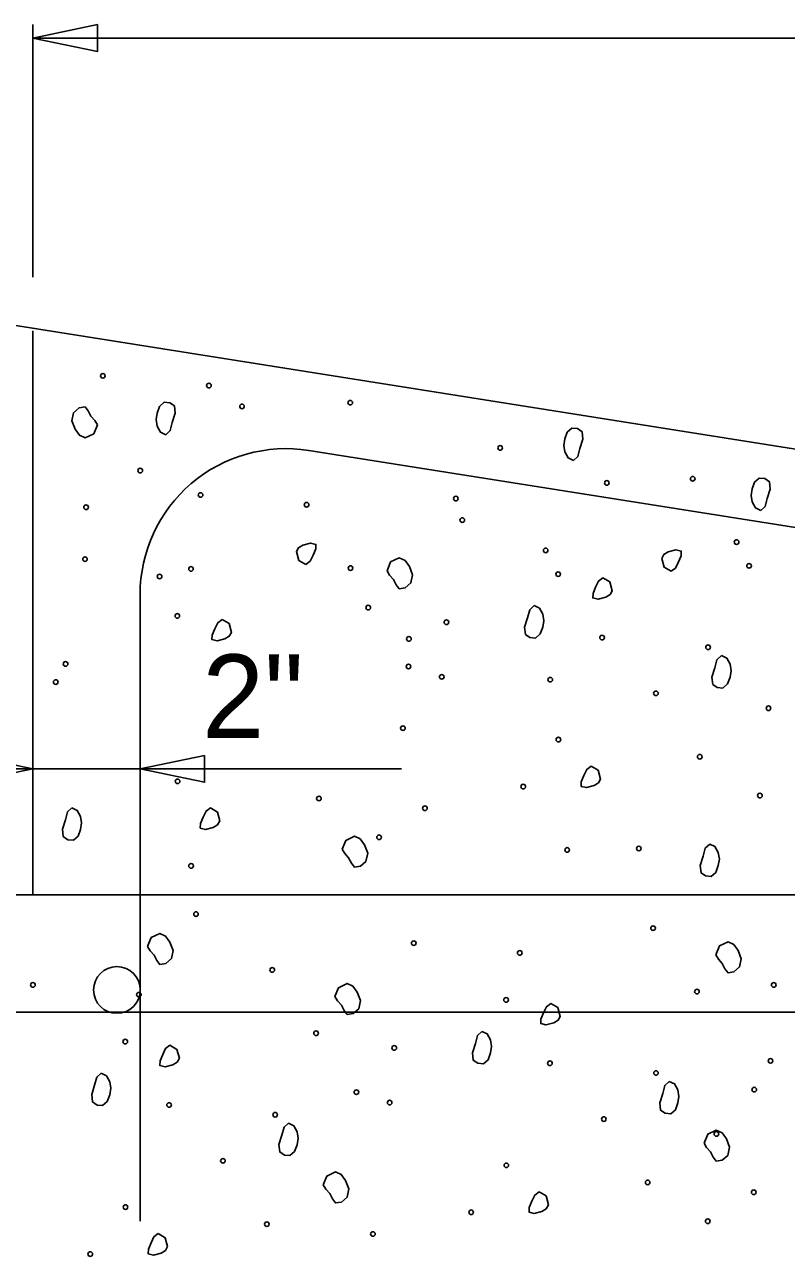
# Model space of a CAD drawing. Extents: x -439.2 to -407.9, y -458.1 to -436.2.
# Drawn here: x -422.056 to -420.686, y -450.425 to -448.209 of the extents above; entities that cross this region are included whole.
import ezdxf

# ---------------------------------------------------------------- set-up
doc = ezdxf.new("R2010")
doc.units = 0
doc.layers.add('Level 4', color=7, linetype='Continuous')
doc.layers.add('Level 45', color=7, linetype='Continuous')

msp = doc.modelspace()

# ---------------------------------------------------------------- linework, layer by layer
at = {"layer": 'Level 4'}
for p, q in [((-422.0412, -448.6637), (-422.0412, -448.2093)), ((-422.0412, -448.2334), (-416.5408, -448.2334)), ((-423.4518, -448.532), (-416.5407, -449.6272)), ((-422.0416, -448.7599), (-422.0416, -449.7752)), ((-421.5448, -448.9753), (-416.9196, -449.7086)), ((-421.8484, -449.2346), (-421.8484, -450.3622)), ((-422.2887, -449.5483), (-421.378, -449.5483)), ((-423.4518, -449.7752), (-416.5407, -449.7752)), ((-423.4518, -449.9863), (-416.6814, -449.9863))]:
    msp.add_line(p, q, dxfattribs=at)
for points in [[(-421.925, -448.2093), (-422.0412, -448.2334), (-421.925, -448.2575)], [(-421.8022, -448.9471), (-421.7943, -448.9397), (-421.7905, -448.9251), (-421.7852, -448.9083), (-421.7866, -448.8952), (-421.7948, -448.8896), (-421.8048, -448.8887), (-421.8132, -448.8961), (-421.8178, -448.9082), (-421.8196, -448.9199), (-421.8178, -448.9316), (-421.8118, -448.9424), (-421.8022, -448.9471)], [(-421.9253, -448.9295), (-421.9318, -448.9452), (-421.9473, -448.9528), (-421.9576, -448.948), (-421.9655, -448.9373), (-421.9712, -448.922), (-421.9681, -448.9074), (-421.9581, -448.8986), (-421.9473, -448.897), (-421.9419, -448.9041), (-421.937, -448.9139), (-421.9299, -448.9215), (-421.9253, -448.9295)], [(-421.0689, -448.9936), (-421.061, -448.9862), (-421.0572, -448.9716), (-421.0519, -448.9548), (-421.0533, -448.9417), (-421.0615, -448.9361), (-421.0715, -448.9352), (-421.0799, -448.9426), (-421.0845, -448.9547), (-421.0863, -448.9664), (-421.0845, -448.9781), (-421.0785, -448.9889), (-421.0689, -448.9936)], [(-420.7319, -449.0836), (-420.7239, -449.0762), (-420.7202, -449.0616), (-420.7149, -449.0448), (-420.7163, -449.0317), (-420.7245, -449.0261), (-420.7345, -449.0252), (-420.7429, -449.0326), (-420.7475, -449.0447), (-420.7493, -449.0564), (-420.7475, -449.0681), (-420.7414, -449.0789), (-420.7319, -449.0836)], [(-421.5503, -449.1807), (-421.5425, -449.1748), (-421.5373, -449.1638), (-421.5325, -449.1526), (-421.5321, -449.1443), (-421.5416, -449.142), (-421.5555, -449.1456), (-421.5632, -449.1504), (-421.5672, -449.1573), (-421.5629, -449.1733), (-421.5503, -449.1807)], [(-420.893, -449.1928), (-420.8852, -449.1869), (-420.88, -449.1759), (-420.8752, -449.1647), (-420.8748, -449.1565), (-420.8843, -449.1541), (-420.8982, -449.1578), (-420.9059, -449.1625), (-420.9098, -449.1695), (-420.9056, -449.1854), (-420.893, -449.1928)], [(-421.4041, -449.1917), (-421.3976, -449.176), (-421.3821, -449.1684), (-421.3718, -449.1732), (-421.3639, -449.1839), (-421.3582, -449.1992), (-421.3613, -449.2138), (-421.3714, -449.2226), (-421.3821, -449.2242), (-421.3875, -449.2171), (-421.3925, -449.2073), (-421.3995, -449.1997), (-421.4041, -449.1917)], [(-421.0158, -449.2044), (-421.0236, -449.2103), (-421.0288, -449.2213), (-421.0335, -449.2325), (-421.034, -449.2407), (-421.0245, -449.2431), (-421.0106, -449.2394), (-421.0028, -449.2347), (-420.9989, -449.2278), (-421.0032, -449.2118), (-421.0158, -449.2044)], [(-421.1396, -449.2545), (-421.1475, -449.2619), (-421.1513, -449.2766), (-421.1566, -449.2933), (-421.1552, -449.3064), (-421.147, -449.312), (-421.137, -449.3129), (-421.1286, -449.3055), (-421.124, -449.2934), (-421.1222, -449.2817), (-421.124, -449.2701), (-421.13, -449.2593), (-421.1396, -449.2545)], [(-421.701, -449.2795), (-421.7088, -449.2854), (-421.714, -449.2963), (-421.7187, -449.3076), (-421.7191, -449.3158), (-421.7097, -449.3182), (-421.6958, -449.3145), (-421.688, -449.3098), (-421.6841, -449.3028), (-421.6883, -449.2869), (-421.701, -449.2795)], [(-420.8026, -449.3445), (-420.8105, -449.3519), (-420.8143, -449.3666), (-420.8195, -449.3833), (-420.8181, -449.3964), (-420.8099, -449.402), (-420.8, -449.4029), (-420.7915, -449.3955), (-420.787, -449.3834), (-420.7852, -449.3717), (-420.787, -449.3601), (-420.793, -449.3493), (-420.8026, -449.3445)], [(-422.1574, -449.5724), (-422.0412, -449.5483), (-422.1574, -449.5242)], [(-421.7323, -449.5242), (-421.8485, -449.5483), (-421.7323, -449.5724)], [(-421.0368, -449.5433), (-421.0446, -449.5492), (-421.0498, -449.5602), (-421.0546, -449.5715), (-421.055, -449.5797), (-421.0455, -449.582), (-421.0317, -449.5784), (-421.0239, -449.5736), (-421.02, -449.5667), (-421.0242, -449.5508), (-421.0368, -449.5433)], [(-421.971, -449.6182), (-421.9789, -449.6256), (-421.9827, -449.6402), (-421.988, -449.657), (-421.9866, -449.6701), (-421.9784, -449.6757), (-421.9684, -449.6766), (-421.96, -449.6692), (-421.9554, -449.6571), (-421.9536, -449.6454), (-421.9554, -449.6337), (-421.9614, -449.6229), (-421.971, -449.6182)], [(-421.722, -449.6184), (-421.7298, -449.6243), (-421.735, -449.6353), (-421.7398, -449.6465), (-421.7402, -449.6548), (-421.7307, -449.6571), (-421.7168, -449.6535), (-421.7091, -449.6487), (-421.7052, -449.6418), (-421.7094, -449.6259), (-421.722, -449.6184)], [(-421.4849, -449.6927), (-421.4783, -449.6769), (-421.4628, -449.6693), (-421.4525, -449.6742), (-421.4446, -449.6849), (-421.4389, -449.7002), (-421.442, -449.7147), (-421.4521, -449.7236), (-421.4628, -449.7251), (-421.4682, -449.7181), (-421.4732, -449.7083), (-421.4802, -449.7007), (-421.4849, -449.6927)], [(-420.8236, -449.6835), (-420.8316, -449.6909), (-420.8353, -449.7055), (-420.8406, -449.7223), (-420.8392, -449.7354), (-420.831, -449.741), (-420.821, -449.7419), (-420.8126, -449.7345), (-420.8081, -449.7224), (-420.8062, -449.7107), (-420.8081, -449.699), (-420.8141, -449.6882), (-420.8236, -449.6835)], [(-421.8349, -449.8677), (-421.8283, -449.8519), (-421.8129, -449.8443), (-421.8026, -449.8492), (-421.7947, -449.8599), (-421.789, -449.8752), (-421.7921, -449.8897), (-421.8021, -449.8986), (-421.8129, -449.9001), (-421.8183, -449.8931), (-421.8232, -449.8833), (-421.8302, -449.8757), (-421.8349, -449.8677)], [(-420.8127, -449.8826), (-420.8061, -449.8669), (-420.7906, -449.8592), (-420.7803, -449.8641), (-420.7725, -449.8748), (-420.7667, -449.8901), (-420.7699, -449.9047), (-420.7799, -449.9135), (-420.7906, -449.9151), (-420.7961, -449.908), (-420.801, -449.8982), (-420.808, -449.8906), (-420.8127, -449.8826)], [(-421.4979, -449.9577), (-421.4913, -449.942), (-421.4758, -449.9343), (-421.4655, -449.9392), (-421.4576, -449.9499), (-421.4519, -449.9652), (-421.455, -449.9798), (-421.4651, -449.9886), (-421.4758, -449.9901), (-421.4813, -449.9831), (-421.4862, -449.9733), (-421.4932, -449.9657), (-421.4979, -449.9577)], [(-421.1095, -449.9704), (-421.1173, -449.9763), (-421.1225, -449.9872), (-421.1272, -449.9985), (-421.1277, -450.0067), (-421.1182, -450.009), (-421.1043, -450.0054), (-421.0965, -450.0006), (-421.0926, -449.9937), (-421.0969, -449.9778), (-421.1095, -449.9704)], [(-421.2333, -450.0205), (-421.2413, -450.0279), (-421.245, -450.0425), (-421.2503, -450.0593), (-421.2489, -450.0724), (-421.2407, -450.078), (-421.2307, -450.0789), (-421.2223, -450.0715), (-421.2178, -450.0594), (-421.2159, -450.0477), (-421.2178, -450.036), (-421.2238, -450.0252), (-421.2333, -450.0205)], [(-421.7947, -450.0454), (-421.8025, -450.0513), (-421.8077, -450.0623), (-421.8124, -450.0736), (-421.8129, -450.0818), (-421.8034, -450.0841), (-421.7895, -450.0805), (-421.7817, -450.0757), (-421.7778, -450.0688), (-421.7821, -450.0529), (-421.7947, -450.0454)], [(-421.9185, -450.0955), (-421.9265, -450.103), (-421.9302, -450.1176), (-421.9355, -450.1344), (-421.9341, -450.1475), (-421.9259, -450.1531), (-421.9159, -450.154), (-421.9075, -450.1466), (-421.903, -450.1345), (-421.9011, -450.1228), (-421.903, -450.1111), (-421.909, -450.1003), (-421.9185, -450.0955)], [(-420.8963, -450.1105), (-420.9042, -450.1179), (-420.908, -450.1325), (-420.9133, -450.1493), (-420.9119, -450.1624), (-420.9037, -450.168), (-420.8937, -450.1689), (-420.8853, -450.1615), (-420.8807, -450.1494), (-420.8789, -450.1377), (-420.8807, -450.126), (-420.8867, -450.1152), (-420.8963, -450.1105)], [(-421.5815, -450.1856), (-421.5894, -450.193), (-421.5932, -450.2076), (-421.5985, -450.2244), (-421.5971, -450.2375), (-421.5889, -450.2431), (-421.5789, -450.244), (-421.5705, -450.2366), (-421.5659, -450.2245), (-421.5641, -450.2128), (-421.5659, -450.2011), (-421.5719, -450.1903), (-421.5815, -450.1856)], [(-420.8338, -450.2216), (-420.8272, -450.2058), (-420.8117, -450.1982), (-420.8014, -450.203), (-420.7935, -450.2138), (-420.7878, -450.229), (-420.7909, -450.2436), (-420.801, -450.2525), (-420.8117, -450.254), (-420.8171, -450.2469), (-420.8221, -450.2371), (-420.8291, -450.2296), (-420.8338, -450.2216)], [(-421.5189, -450.2966), (-421.5124, -450.2809), (-421.4969, -450.2733), (-421.4866, -450.2781), (-421.4787, -450.2889), (-421.473, -450.3041), (-421.4761, -450.3187), (-421.4862, -450.3276), (-421.4969, -450.3291), (-421.5023, -450.322), (-421.5073, -450.3122), (-421.5143, -450.3046), (-421.5189, -450.2966)], [(-421.1306, -450.3093), (-421.1384, -450.3152), (-421.1436, -450.3262), (-421.1483, -450.3374), (-421.1487, -450.3457), (-421.1393, -450.348), (-421.1254, -450.3444), (-421.1176, -450.3396), (-421.1137, -450.3327), (-421.1179, -450.3167), (-421.1306, -450.3093)], [(-421.8158, -450.3844), (-421.8235, -450.3903), (-421.8287, -450.4013), (-421.8335, -450.4125), (-421.8339, -450.4208), (-421.8245, -450.4231), (-421.8106, -450.4195), (-421.8028, -450.4147), (-421.7989, -450.4078), (-421.8031, -450.3918), (-421.8158, -450.3844)]]:
    msp.add_lwpolyline(points, close=True, dxfattribs=at)
msp.add_circle((-421.8901, -449.9461), 0.042, dxfattribs=at)
for centre, radius, start, end in [((-421.9154, -448.8411), 0.00416, 0, 180), ((-421.9154, -448.8411), 0.00416, 180, 0), ((-421.7246, -448.8586), 0.00416, 0, 180), ((-421.7246, -448.8586), 0.00416, 180, 0), ((-421.6651, -448.8961), 0.00416, 0, 180), ((-421.6651, -448.8961), 0.00416, 180, 0), ((-421.4703, -448.8894), 0.00416, 0, 180), ((-421.4703, -448.8894), 0.00416, 180, 0), ((-421.5859, -449.2346), 0.2625, 80.9913, 180), ((-421.2006, -448.9708), 0.00416, 0, 180), ((-421.2006, -448.9708), 0.00416, 180, 0), ((-421.8482, -449.0116), 0.00416, 0, 180), ((-421.8482, -449.0116), 0.00416, 180, 0), ((-421.0087, -449.0338), 0.00416, 0, 180), ((-420.8542, -449.0262), 0.00416, 0, 180), ((-420.8542, -449.0262), 0.00416, 180, 0), ((-421.7396, -449.0555), 0.00416, 0, 180), ((-421.0087, -449.0338), 0.00416, 180, 0), ((-421.9456, -449.0775), 0.00416, 0, 180), ((-421.7396, -449.0555), 0.00416, 180, 0), ((-421.5488, -449.0731), 0.00416, 0, 180), ((-421.5488, -449.0731), 0.00416, 180, 0), ((-421.2803, -449.0619), 0.00416, 0, 180), ((-421.2803, -449.0619), 0.00416, 180, 0), ((-421.9456, -449.0775), 0.00416, 180, 0), ((-421.2687, -449.1007), 0.00416, 0, 180), ((-421.2687, -449.1007), 0.00416, 180, 0), ((-420.7753, -449.1402), 0.00416, 0, 180), ((-420.7753, -449.1402), 0.00416, 180, 0), ((-421.1187, -449.1552), 0.00416, 0, 180), ((-421.1187, -449.1552), 0.00416, 180, 0), ((-421.9475, -449.171), 0.00416, 0, 180), ((-421.9475, -449.171), 0.00416, 180, 0), ((-421.7568, -449.1885), 0.00416, 0, 180), ((-421.4699, -449.1871), 0.00416, 0, 180), ((-420.7528, -449.183), 0.00416, 0, 180), ((-420.7528, -449.183), 0.00416, 180, 0), ((-421.8133, -449.2021), 0.00416, 0, 180), ((-421.8133, -449.2021), 0.00416, 180, 0), ((-421.7568, -449.1885), 0.00416, 180, 0), ((-421.4699, -449.1871), 0.00416, 180, 0), ((-421.0962, -449.198), 0.00416, 0, 180), ((-421.0962, -449.198), 0.00416, 180, 0), ((-421.7814, -449.2731), 0.00416, 0, 180), ((-421.7814, -449.2731), 0.00416, 180, 0), ((-421.438, -449.2581), 0.00416, 0, 180), ((-421.438, -449.2581), 0.00416, 180, 0), ((-421.2973, -449.2844), 0.00416, 0, 180), ((-421.2973, -449.2844), 0.00416, 180, 0), ((-421.3648, -449.3144), 0.00416, 0, 180), ((-421.3648, -449.3144), 0.00416, 180, 0), ((-421.0172, -449.312), 0.00416, 0, 180), ((-421.0172, -449.312), 0.00416, 180, 0), ((-420.8265, -449.3295), 0.00416, 0, 180), ((-420.8265, -449.3295), 0.00416, 180, 0), ((-421.9825, -449.3595), 0.00416, 0, 180), ((-421.9825, -449.3595), 0.00416, 180, 0), ((-421.3655, -449.3641), 0.00416, 0, 180), ((-421.3655, -449.3641), 0.00416, 180, 0), ((-421.3057, -449.3827), 0.00416, 0, 180), ((-421.3057, -449.3827), 0.00416, 180, 0), ((-421.1104, -449.3878), 0.00416, 0, 180), ((-422.0002, -449.3921), 0.00416, 0, 180), ((-422.0002, -449.3921), 0.00416, 180, 0), ((-421.1104, -449.3878), 0.00416, 180, 0), ((-420.9204, -449.4124), 0.00416, 0, 180), ((-420.9204, -449.4124), 0.00416, 180, 0), ((-420.7178, -449.4392), 0.00416, 0, 180), ((-420.7178, -449.4392), 0.00416, 180, 0), ((-421.3755, -449.475), 0.00416, 0, 180), ((-421.3755, -449.475), 0.00416, 180, 0), ((-421.0958, -449.4956), 0.00416, 0, 180), ((-421.0958, -449.4956), 0.00416, 180, 0), ((-420.8415, -449.5265), 0.00416, 0, 180), ((-420.8415, -449.5265), 0.00416, 180, 0), ((-421.781, -449.5707), 0.00416, 0, 180), ((-421.781, -449.5707), 0.00416, 180, 0), ((-421.1591, -449.5802), 0.00416, 0, 180), ((-421.1591, -449.5802), 0.00416, 180, 0), ((-421.5267, -449.6016), 0.00416, 0, 180), ((-421.5267, -449.6016), 0.00416, 180, 0), ((-420.7333, -449.5963), 0.00416, 0, 180), ((-420.7333, -449.5963), 0.00416, 180, 0), ((-421.3359, -449.6191), 0.00416, 0, 180), ((-421.3359, -449.6191), 0.00416, 180, 0), ((-421.4185, -449.6714), 0.00416, 0, 180), ((-421.4185, -449.6714), 0.00416, 180, 0), ((-421.0801, -449.6942), 0.00416, 0, 180), ((-421.0801, -449.6942), 0.00416, 180, 0), ((-420.9511, -449.6915), 0.00416, 0, 180), ((-420.9511, -449.6915), 0.00416, 180, 0), ((-421.7566, -449.7228), 0.00416, 0, 180), ((-421.7566, -449.7228), 0.00416, 180, 0), ((-421.7478, -449.8096), 0.00416, 0, 180), ((-421.7478, -449.8096), 0.00416, 180, 0), ((-420.9255, -449.8349), 0.00416, 0, 180), ((-420.9255, -449.8349), 0.00416, 180, 0), ((-421.3561, -449.8619), 0.00416, 0, 180), ((-421.3561, -449.8619), 0.00416, 180, 0), ((-421.1653, -449.8794), 0.00416, 0, 180), ((-421.1653, -449.8794), 0.00416, 180, 0), ((-421.6106, -449.91), 0.00416, 0, 180), ((-421.6106, -449.91), 0.00416, 180, 0), ((-422.0413, -449.937), 0.00416, 0, 180), ((-422.0413, -449.937), 0.00416, 180, 0), ((-420.7084, -449.937), 0.00416, 0, 180), ((-420.7084, -449.937), 0.00416, 180, 0), ((-421.8505, -449.9545), 0.00416, 0, 180), ((-421.8505, -449.9545), 0.00416, 180, 0), ((-421.1899, -449.9639), 0.00416, 0, 180), ((-420.8465, -449.949), 0.00416, 0, 180), ((-420.8465, -449.949), 0.00416, 180, 0), ((-421.1899, -449.9639), 0.00416, 180, 0), ((-421.5317, -450.024), 0.00416, 0, 180), ((-421.5317, -450.024), 0.00416, 180, 0), ((-421.8751, -450.039), 0.00416, 0, 180), ((-421.8751, -450.039), 0.00416, 180, 0), ((-421.3911, -450.0503), 0.00416, 0, 180), ((-421.3911, -450.0503), 0.00416, 180, 0), ((-420.7142, -450.0736), 0.00416, 0, 180), ((-421.111, -450.078), 0.00416, 0, 180), ((-421.111, -450.078), 0.00416, 180, 0), ((-420.9202, -450.0955), 0.00416, 0, 180), ((-420.7142, -450.0736), 0.00416, 180, 0), ((-420.9202, -450.0955), 0.00416, 180, 0), ((-421.4592, -450.13), 0.00416, 0, 180), ((-421.4592, -450.13), 0.00416, 180, 0), ((-420.7434, -450.1254), 0.00416, 0, 180), ((-420.7434, -450.1254), 0.00416, 180, 0), ((-421.7962, -450.153), 0.00416, 0, 180), ((-421.7962, -450.153), 0.00416, 180, 0), ((-421.3994, -450.1487), 0.00416, 0, 180), ((-421.3994, -450.1487), 0.00416, 180, 0), ((-421.6054, -450.1706), 0.00416, 0, 180), ((-421.6054, -450.1706), 0.00416, 180, 0), ((-421.0141, -450.1784), 0.00416, 0, 180), ((-421.0141, -450.1784), 0.00416, 180, 0), ((-420.8116, -450.2051), 0.00416, 0, 180), ((-420.8116, -450.2051), 0.00416, 180, 0), ((-421.6993, -450.2535), 0.00416, 0, 180), ((-421.6993, -450.2535), 0.00416, 180, 0), ((-421.1895, -450.2616), 0.00416, 0, 180), ((-421.1895, -450.2616), 0.00416, 180, 0), ((-420.9352, -450.2924), 0.00416, 0, 180), ((-420.9352, -450.2924), 0.00416, 180, 0), ((-420.7444, -450.31), 0.00416, 0, 180), ((-420.7444, -450.31), 0.00416, 180, 0), ((-421.8747, -450.3367), 0.00416, 0, 180), ((-421.8747, -450.3367), 0.00416, 180, 0), ((-421.2528, -450.3461), 0.00416, 0, 180), ((-421.2528, -450.3461), 0.00416, 180, 0), ((-420.8271, -450.3622), 0.00416, 0, 180), ((-421.6204, -450.3675), 0.00416, 0, 180), ((-421.6204, -450.3675), 0.00416, 180, 0), ((-421.4296, -450.3851), 0.00416, 0, 180), ((-420.8271, -450.3622), 0.00416, 180, 0), ((-421.4296, -450.3851), 0.00416, 180, 0), ((-421.938, -450.4212), 0.00416, 0, 180), ((-421.938, -450.4212), 0.00416, 180, 0)]:
    msp.add_arc(centre, radius, start, end, dxfattribs=at)

# ---------------------------------------------------------------- texts
at = {"layer": 'Level 45'}
msp.add_text('2"', height=0.15, dxfattribs=at).set_placement((-421.7367, -449.4925))

doc.saveas('drawing.dxf')
